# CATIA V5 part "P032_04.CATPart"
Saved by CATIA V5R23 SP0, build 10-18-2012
Part number: 05-LICP-T02-E-S03-P032_04
Bounding box of the stored display mesh (mm): x 18.795 to 21, y -14 to 14, z -13.955 to 13.955
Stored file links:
  C:\wamp\www\COURS\CONCEPTION GMP1\TITRE 02-SEMESTRE 2\03-TP7-PRESSE MECANIQUE\eleve\P032_04.CATPart
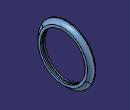
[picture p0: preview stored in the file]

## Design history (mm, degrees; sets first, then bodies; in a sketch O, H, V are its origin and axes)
Body1 (main body)
  Solid1: solid without history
